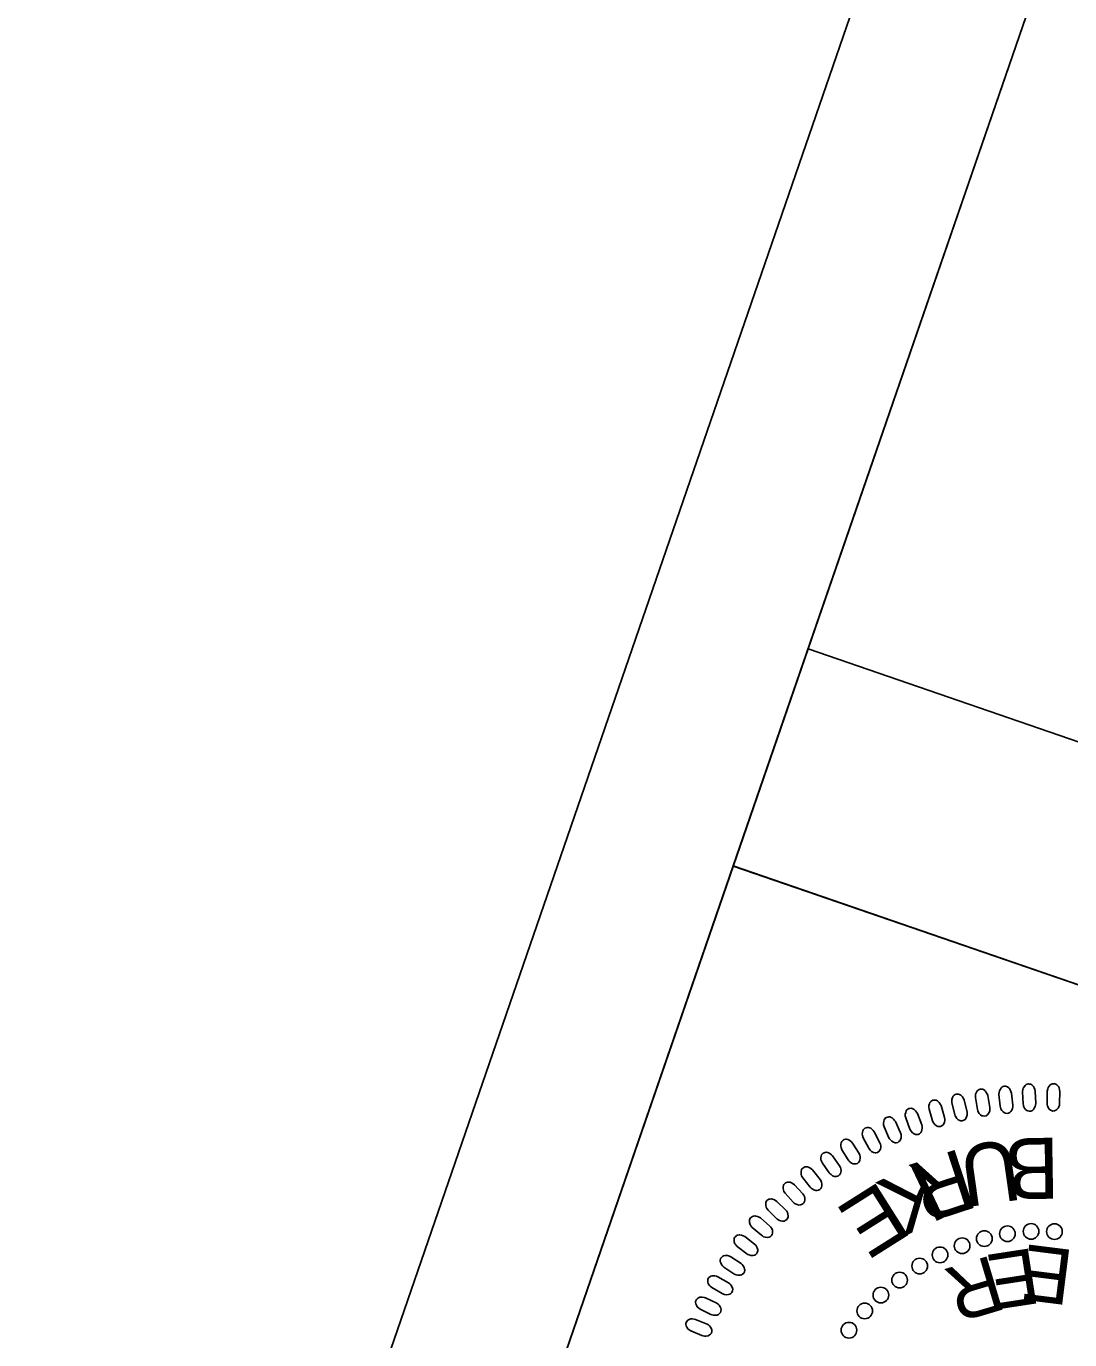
# Model space of a CAD drawing. Extents: x 479650 to 481768, y 492454 to 494037.
# Drawn here: x 479650.3 to 479757, y 493111.2 to 493245.4 of the extents above; entities that cross this region are included whole.
import ezdxf

# ---------------------------------------------------------------- set-up
doc = ezdxf.new("R2010")
doc.units = 0
for name, color, linetype in [('Sheet PE Seal Cell', 7, 'Continuous'), ('Sheet Plan CELL', 7, 'Continuous'), ('Sheet Plot Border Outside CELL', 7, 'Continuous'), ('Sheet Sticker Exception Certification CELL', 7, 'Continuous')]:
    doc.layers.add(name, color=color, linetype=linetype)

msp = doc.modelspace()

# ---------------------------------------------------------------- linework, layer by layer
at = {"layer": 'Sheet PE Seal Cell'}
for points in [[(479747.57, 493134.7), (479747.36, 493135.91), (479747.36, 493136.13), (479747.39, 493136.27), (479747.47, 493136.46), (479747.55, 493136.59), (479747.65, 493136.68), (479747.74, 493136.74), (479747.85, 493136.78), (479747.96, 493136.78), (479748.09, 493136.77), (479748.2, 493136.73), (479748.32, 493136.65), (479748.39, 493136.58), (479748.48, 493136.44), (479748.57, 493136.28), (479748.62, 493136.12), (479748.84, 493134.89), (479748.85, 493134.71), (479748.83, 493134.57), (479748.77, 493134.4), (479748.68, 493134.24), (479748.6, 493134.14), (479748.45, 493134.06), (479748.31, 493134.01), (479748.16, 493134.03), (479748.04, 493134.06), (479747.9, 493134.14), (479747.76, 493134.28), (479747.66, 493134.45), (479747.61, 493134.57)], [(479749.91, 493135.02), (479749.77, 493136.24), (479749.79, 493136.46), (479749.82, 493136.6), (479749.92, 493136.78), (479750, 493136.9), (479750.1, 493137), (479750.2, 493137.05), (479750.31, 493137.08), (479750.43, 493137.07), (479750.55, 493137.05), (479750.66, 493137.01), (479750.77, 493136.92), (479750.84, 493136.84), (479750.93, 493136.7), (479751, 493136.53), (479751.04, 493136.37), (479751.19, 493135.13), (479751.18, 493134.95), (479751.15, 493134.81), (479751.08, 493134.64), (479750.98, 493134.49), (479750.9, 493134.4), (479750.75, 493134.33), (479750.6, 493134.29), (479750.45, 493134.31), (479750.34, 493134.35), (479750.2, 493134.44), (479750.06, 493134.59), (479749.98, 493134.77), (479749.93, 493134.89)], [(479752.24, 493135.28), (479752.19, 493136.5), (479752.22, 493136.72), (479752.26, 493136.86), (479752.37, 493137.04), (479752.46, 493137.15), (479752.57, 493137.24), (479752.67, 493137.28), (479752.78, 493137.31), (479752.89, 493137.29), (479753.02, 493137.27), (479753.12, 493137.21), (479753.23, 493137.12), (479753.3, 493137.04), (479753.37, 493136.89), (479753.44, 493136.72), (479753.47, 493136.56), (479753.53, 493135.3), (479753.52, 493135.13), (479753.48, 493134.99), (479753.39, 493134.83), (479753.29, 493134.68), (479753.2, 493134.6), (479753.04, 493134.53), (479752.89, 493134.51), (479752.74, 493134.54), (479752.63, 493134.59), (479752.5, 493134.68), (479752.38, 493134.84), (479752.3, 493135.02), (479752.27, 493135.15)], [(479754.69, 493135.34), (479754.71, 493136.57), (479754.76, 493136.79), (479754.81, 493136.93), (479754.92, 493137.09), (479755.02, 493137.2), (479755.14, 493137.28), (479755.24, 493137.32), (479755.36, 493137.33), (479755.47, 493137.31), (479755.59, 493137.28), (479755.69, 493137.22), (479755.79, 493137.12), (479755.85, 493137.04), (479755.92, 493136.89), (479755.97, 493136.7), (479755.99, 493136.54), (479755.98, 493135.29), (479755.95, 493135.12), (479755.9, 493134.98), (479755.81, 493134.82), (479755.7, 493134.69), (479755.6, 493134.61), (479755.44, 493134.55), (479755.29, 493134.53), (479755.14, 493134.58), (479755.04, 493134.63), (479754.91, 493134.73), (479754.8, 493134.9), (479754.73, 493135.08), (479754.7, 493135.21)], [(479742.98, 493133.54), (479742.63, 493134.72), (479742.6, 493134.94), (479742.6, 493135.09), (479742.66, 493135.28), (479742.72, 493135.42), (479742.81, 493135.52), (479742.9, 493135.59), (479743, 493135.64), (479743.11, 493135.66), (479743.23, 493135.66), (479743.35, 493135.64), (479743.48, 493135.57), (479743.56, 493135.51), (479743.67, 493135.39), (479743.78, 493135.24), (479743.85, 493135.09), (479744.22, 493133.89), (479744.25, 493133.72), (479744.25, 493133.58), (479744.21, 493133.4), (479744.14, 493133.23), (479744.07, 493133.13), (479743.94, 493133.02), (479743.8, 493132.96), (479743.65, 493132.95), (479743.53, 493132.97), (479743.38, 493133.03), (479743.22, 493133.16), (479743.1, 493133.31), (479743.03, 493133.42)], [(479745.25, 493134.17), (479744.97, 493135.36), (479744.96, 493135.58), (479744.97, 493135.73), (479745.04, 493135.92), (479745.11, 493136.05), (479745.2, 493136.15), (479745.3, 493136.22), (479745.4, 493136.26), (479745.51, 493136.27), (479745.64, 493136.27), (479745.75, 493136.23), (479745.88, 493136.16), (479745.95, 493136.1), (479746.06, 493135.97), (479746.16, 493135.81), (479746.21, 493135.66), (479746.51, 493134.44), (479746.53, 493134.27), (479746.52, 493134.12), (479746.47, 493133.94), (479746.39, 493133.78), (479746.31, 493133.68), (479746.17, 493133.59), (479746.03, 493133.53), (479745.88, 493133.54), (479745.77, 493133.56), (479745.62, 493133.63), (479745.46, 493133.77), (479745.36, 493133.93), (479745.3, 493134.04)], [(479738.53, 493131.8), (479738.03, 493132.92), (479737.98, 493133.14), (479737.97, 493133.29), (479738, 493133.49), (479738.04, 493133.63), (479738.11, 493133.75), (479738.19, 493133.83), (479738.29, 493133.89), (479738.4, 493133.92), (479738.52, 493133.94), (479738.64, 493133.93), (479738.77, 493133.88), (479738.86, 493133.83), (479738.98, 493133.72), (479739.11, 493133.58), (479739.2, 493133.45), (479739.72, 493132.3), (479739.77, 493132.14), (479739.78, 493131.99), (479739.77, 493131.81), (479739.72, 493131.64), (479739.67, 493131.52), (479739.55, 493131.41), (479739.42, 493131.33), (479739.27, 493131.3), (479739.15, 493131.3), (479738.99, 493131.34), (479738.82, 493131.45), (479738.68, 493131.59), (479738.6, 493131.69)], [(479740.67, 493132.68), (479740.24, 493133.83), (479740.2, 493134.05), (479740.2, 493134.2), (479740.24, 493134.4), (479740.29, 493134.54), (479740.37, 493134.65), (479740.46, 493134.72), (479740.55, 493134.78), (479740.67, 493134.8), (479740.79, 493134.82), (479740.91, 493134.8), (479741.04, 493134.74), (479741.12, 493134.69), (479741.24, 493134.57), (479741.36, 493134.42), (479741.44, 493134.28), (479741.88, 493133.11), (479741.92, 493132.94), (479741.93, 493132.8), (479741.9, 493132.61), (479741.85, 493132.44), (479741.78, 493132.34), (479741.66, 493132.22), (479741.52, 493132.15), (479741.37, 493132.14), (479741.25, 493132.15), (479741.1, 493132.2), (479740.93, 493132.31), (479740.8, 493132.46), (479740.73, 493132.57)], [(479736.46, 493130.73), (479735.89, 493131.81), (479735.82, 493132.02), (479735.8, 493132.17), (479735.82, 493132.37), (479735.85, 493132.52), (479735.92, 493132.64), (479735.99, 493132.72), (479736.08, 493132.79), (479736.19, 493132.83), (479736.31, 493132.86), (479736.43, 493132.85), (479736.57, 493132.81), (479736.66, 493132.77), (479736.79, 493132.67), (479736.92, 493132.54), (479737.02, 493132.41), (479737.61, 493131.3), (479737.67, 493131.14), (479737.69, 493130.99), (479737.69, 493130.81), (479737.66, 493130.64), (479737.61, 493130.52), (479737.5, 493130.39), (479737.37, 493130.31), (479737.22, 493130.27), (479737.11, 493130.27), (479736.95, 493130.3), (479736.76, 493130.39), (479736.62, 493130.52), (479736.53, 493130.62)], [(479734.36, 493129.53), (479733.72, 493130.58), (479733.64, 493130.79), (479733.61, 493130.93), (479733.62, 493131.14), (479733.65, 493131.28), (479733.7, 493131.41), (479733.77, 493131.5), (479733.85, 493131.57), (479733.96, 493131.61), (479734.08, 493131.65), (479734.2, 493131.65), (479734.34, 493131.62), (479734.43, 493131.59), (479734.57, 493131.49), (479734.71, 493131.37), (479734.81, 493131.25), (479735.47, 493130.18), (479735.54, 493130.02), (479735.58, 493129.88), (479735.58, 493129.7), (479735.56, 493129.52), (479735.52, 493129.4), (479735.42, 493129.27), (479735.3, 493129.17), (479735.15, 493129.13), (479735.04, 493129.12), (479734.88, 493129.13), (479734.69, 493129.22), (479734.53, 493129.34), (479734.44, 493129.43)], [(479732.42, 493128.21), (479731.72, 493129.22), (479731.62, 493129.42), (479731.58, 493129.56), (479731.58, 493129.77), (479731.6, 493129.91), (479731.64, 493130.04), (479731.7, 493130.14), (479731.79, 493130.22), (479731.89, 493130.26), (479732, 493130.31), (479732.12, 493130.32), (479732.27, 493130.3), (479732.36, 493130.27), (479732.5, 493130.18), (479732.66, 493130.07), (479732.77, 493129.95), (479733.49, 493128.93), (479733.57, 493128.77), (479733.61, 493128.63), (479733.63, 493128.45), (479733.62, 493128.27), (479733.59, 493128.15), (479733.49, 493128.01), (479733.38, 493127.91), (479733.23, 493127.86), (479733.12, 493127.84), (479732.96, 493127.85), (479732.76, 493127.92), (479732.61, 493128.03), (479732.51, 493128.12)], [(479730.48, 493126.75), (479729.71, 493127.71), (479729.6, 493127.91), (479729.56, 493128.05), (479729.54, 493128.25), (479729.55, 493128.4), (479729.59, 493128.53), (479729.64, 493128.62), (479729.72, 493128.71), (479729.82, 493128.76), (479729.93, 493128.82), (479730.05, 493128.83), (479730.19, 493128.82), (479730.29, 493128.8), (479730.44, 493128.72), (479730.59, 493128.62), (479730.71, 493128.51), (479731.5, 493127.53), (479731.59, 493127.38), (479731.64, 493127.25), (479731.67, 493127.07), (479731.67, 493126.89), (479731.64, 493126.76), (479731.56, 493126.62), (479731.45, 493126.51), (479731.31, 493126.45), (479731.2, 493126.42), (479731.04, 493126.42), (479730.84, 493126.48), (479730.67, 493126.58), (479730.57, 493126.66)], [(479728.75, 493125.22), (479727.92, 493126.13), (479727.8, 493126.32), (479727.75, 493126.45), (479727.72, 493126.66), (479727.72, 493126.8), (479727.75, 493126.94), (479727.8, 493127.04), (479727.87, 493127.13), (479727.96, 493127.19), (479728.07, 493127.24), (479728.19, 493127.27), (479728.33, 493127.27), (479728.43, 493127.25), (479728.58, 493127.18), (479728.75, 493127.09), (479728.87, 493126.99), (479729.72, 493126.06), (479729.82, 493125.92), (479729.88, 493125.79), (479729.92, 493125.61), (479729.93, 493125.43), (479729.91, 493125.3), (479729.83, 493125.15), (479729.74, 493125.04), (479729.6, 493124.97), (479729.49, 493124.94), (479729.33, 493124.92), (479729.13, 493124.97), (479728.95, 493125.06), (479728.84, 493125.13)], [(479727.06, 493123.53), (479726.18, 493124.39), (479726.05, 493124.57), (479725.98, 493124.7), (479725.94, 493124.9), (479725.93, 493125.05), (479725.95, 493125.18), (479725.99, 493125.28), (479726.06, 493125.38), (479726.15, 493125.44), (479726.26, 493125.51), (479726.37, 493125.54), (479726.52, 493125.55), (479726.61, 493125.54), (479726.77, 493125.48), (479726.94, 493125.4), (479727.07, 493125.3), (479727.97, 493124.43), (479728.08, 493124.3), (479728.15, 493124.17), (479728.2, 493123.99), (479728.22, 493123.81), (479728.21, 493123.69), (479728.14, 493123.53), (479728.05, 493123.41), (479727.92, 493123.33), (479727.81, 493123.29), (479727.65, 493123.27), (479727.45, 493123.3), (479727.27, 493123.38), (479727.16, 493123.45)], [(479725.49, 493121.83), (479724.56, 493122.63), (479724.42, 493122.8), (479724.35, 493122.93), (479724.29, 493123.13), (479724.27, 493123.27), (479724.29, 493123.41), (479724.32, 493123.51), (479724.38, 493123.61), (479724.47, 493123.68), (479724.57, 493123.75), (479724.68, 493123.79), (479724.83, 493123.81), (479724.93, 493123.8), (479725.08, 493123.76), (479725.26, 493123.68), (479725.4, 493123.6), (479726.35, 493122.78), (479726.47, 493122.66), (479726.54, 493122.53), (479726.61, 493122.36), (479726.64, 493122.18), (479726.64, 493122.06), (479726.58, 493121.9), (479726.5, 493121.77), (479726.37, 493121.69), (479726.27, 493121.64), (479726.11, 493121.61), (479725.9, 493121.63), (479725.72, 493121.69), (479725.6, 493121.76)], [(479723.99, 493119.94), (479723.02, 493120.67), (479722.86, 493120.84), (479722.78, 493120.96), (479722.71, 493121.15), (479722.69, 493121.3), (479722.69, 493121.44), (479722.72, 493121.54), (479722.77, 493121.64), (479722.86, 493121.72), (479722.95, 493121.8), (479723.06, 493121.85), (479723.21, 493121.87), (479723.3, 493121.87), (479723.46, 493121.83), (479723.64, 493121.77), (479723.79, 493121.7), (479724.79, 493120.94), (479724.91, 493120.82), (479725, 493120.7), (479725.07, 493120.54), (479725.12, 493120.36), (479725.12, 493120.24), (479725.07, 493120.08), (479725, 493119.94), (479724.88, 493119.85), (479724.78, 493119.8), (479724.62, 493119.75), (479724.41, 493119.76), (479724.23, 493119.82), (479724.11, 493119.87)], [(479722.68, 493117.88), (479721.66, 493118.56), (479721.5, 493118.71), (479721.41, 493118.83), (479721.33, 493119.02), (479721.29, 493119.16), (479721.29, 493119.3), (479721.31, 493119.41), (479721.36, 493119.51), (479721.43, 493119.6), (479721.52, 493119.68), (479721.63, 493119.73), (479721.77, 493119.77), (479721.87, 493119.77), (479722.03, 493119.75), (479722.22, 493119.7), (479722.36, 493119.63), (479723.42, 493118.94), (479723.54, 493118.83), (479723.64, 493118.71), (479723.72, 493118.55), (479723.77, 493118.38), (479723.79, 493118.26), (479723.75, 493118.09), (479723.69, 493117.96), (479723.57, 493117.85), (479723.47, 493117.79), (479723.32, 493117.74), (479723.11, 493117.74), (479722.92, 493117.78), (479722.8, 493117.83)], [(479721.48, 493115.87), (479720.41, 493116.48), (479720.24, 493116.62), (479720.15, 493116.73), (479720.06, 493116.92), (479720.01, 493117.05), (479720, 493117.19), (479720.01, 493117.3), (479720.05, 493117.41), (479720.12, 493117.5), (479720.21, 493117.59), (479720.31, 493117.65), (479720.45, 493117.69), (479720.55, 493117.7), (479720.72, 493117.68), (479720.9, 493117.65), (479721.05, 493117.59), (479722.14, 493116.97), (479722.28, 493116.86), (479722.38, 493116.76), (479722.47, 493116.6), (479722.54, 493116.43), (479722.56, 493116.31), (479722.53, 493116.14), (479722.48, 493116), (479722.37, 493115.89), (479722.27, 493115.83), (479722.12, 493115.77), (479721.92, 493115.75), (479721.73, 493115.78), (479721.6, 493115.82)], [(479720.33, 493113.74), (479719.23, 493114.28), (479719.05, 493114.41), (479718.94, 493114.52), (479718.84, 493114.7), (479718.78, 493114.83), (479718.76, 493114.97), (479718.77, 493115.08), (479718.81, 493115.19), (479718.87, 493115.28), (479718.95, 493115.38), (479719.05, 493115.44), (479719.19, 493115.49), (479719.29, 493115.51), (479719.45, 493115.5), (479719.64, 493115.48), (479719.79, 493115.43), (479720.92, 493114.88), (479721.06, 493114.78), (479721.17, 493114.68), (479721.27, 493114.53), (479721.35, 493114.37), (479721.38, 493114.25), (479721.36, 493114.08), (479721.31, 493113.94), (479721.21, 493113.82), (479721.12, 493113.75), (479720.97, 493113.68), (479720.77, 493113.65), (479720.58, 493113.67), (479720.45, 493113.7)], [(479719.41, 493111.58), (479718.27, 493112.05), (479718.09, 493112.17), (479717.98, 493112.27), (479717.86, 493112.44), (479717.8, 493112.58), (479717.77, 493112.71), (479717.77, 493112.82), (479717.8, 493112.93), (479717.86, 493113.03), (479717.93, 493113.13), (479718.03, 493113.2), (479718.16, 493113.26), (479718.26, 493113.28), (479718.42, 493113.29), (479718.61, 493113.27), (479718.77, 493113.23), (479719.93, 493112.76), (479720.08, 493112.67), (479720.19, 493112.58), (479720.3, 493112.43), (479720.39, 493112.27), (479720.42, 493112.15), (479720.42, 493111.99), (479720.38, 493111.84), (479720.28, 493111.72), (479720.2, 493111.64), (479720.06, 493111.56), (479719.85, 493111.52), (479719.66, 493111.52), (479719.53, 493111.55)]]:
    msp.add_lwpolyline(points, close=True, dxfattribs=at)
for centre in [(479753.06, 493122.23), (479755.45, 493122.21), (479746.01, 493120.76), (479748.28, 493121.49), (479750.64, 493121.99), (479743.75, 493119.83), (479741.67, 493118.69), (479739.62, 493117.25), (479737.7, 493115.72), (479736.05, 493114.1), (479734.44, 493112.13)]:
    msp.add_circle(centre, 0.801, dxfattribs=at)
at = {"layer": 'Sheet Plan CELL'}
for points in [[(479673.72, 493017.72), (481091.94, 492529.09), (481433.97, 493521.82), (480015.77, 494010.44)], [(481433.97, 493521.82), (481091.97, 492529.1), (479862.87, 492952.53), (479911.74, 493094.42), (479722.62, 493159.59), (480015.77, 494010.44)], [(479780.52, 493020.65), (479685.98, 493053.21), (479722.62, 493159.59), (479817.17, 493127.03)]]:
    msp.add_lwpolyline(points, close=True, dxfattribs=at)
at = {"layer": 'Sheet Plot Border Outside CELL'}
msp.add_lwpolyline([(481598.71, 493488.87), (480007.03, 494037.26), (479650.34, 493001.99), (481242.02, 492453.59)], close=True, dxfattribs=at)
at = {"layer": 'Sheet Sticker Exception Certification CELL'}
for p, q in [((479722.62, 493159.59), (479730.28, 493181.81)), ((479722.62, 493159.59), (479730.28, 493181.81)), ((479730.27, 493181.8), (479919.4, 493116.63)), ((479730.27, 493181.8), (479919.4, 493116.63)), ((479911.74, 493094.42), (479722.62, 493159.58)), ((479911.74, 493094.42), (479722.62, 493159.58))]:
    msp.add_line(p, q, dxfattribs=at)

# ---------------------------------------------------------------- texts
at = {"layer": 'Sheet PE Seal Cell'}
for s, height, rotation, p in [('U', 6.24, 188.037, (479751.4, 493131.7)), ('B', 6.24, 180.9201, (479755.9, 493131.82)), ('R', 6.24, 198.1368, (479745.89, 493130.77)), ('K', 6.24, 205.4118, (479742.06, 493129.56)), ('E', 6.24, 212.2575, (479737.74, 493127.48)), ('E', 5.67, 188.713, (479753.34, 493120.56)), ('E', 5.67, 172.8334, (479757.56, 493120.29)), ('R', 5.67, 196.6528, (479749.1, 493119.84))]:
    msp.add_text(s, height=height, rotation=rotation, dxfattribs=at).set_placement(p)

doc.saveas('drawing.dxf')
